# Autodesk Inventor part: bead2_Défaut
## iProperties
Shininess: 64.0
Length Units: 11269
Angle Units: 11279
Time Units: 11290
Mass Units: 11283
Length Display Precision: 3
Angle Display Precision: 2
Compacted: True
Part Number: bead2_Défaut
Document SubType Name: Modeling
Created: 2006-01
Material: Par défaut
Designer: Fricot
Density: 0.0
Volumn: 0.0
Area: 0.0
PropertySet Name: Model Information
Control State: 0
Master: False
Checked Out: False
Author: Fricot
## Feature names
1. Base1
